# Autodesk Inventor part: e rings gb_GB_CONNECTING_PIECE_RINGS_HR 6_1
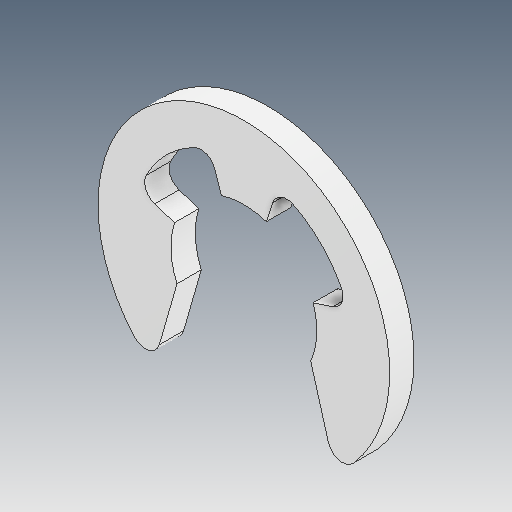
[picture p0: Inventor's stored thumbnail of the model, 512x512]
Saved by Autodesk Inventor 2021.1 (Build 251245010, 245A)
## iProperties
Created: 2021-05
Part Number: e rings gb_GB_CONNECTING_PIECE_RINGS_HR 6_1
Material: Ogólny
Document SubType Name: Modeling
Designer: user
Density: 1 g/cm^3
Appearance: Domyślna
Author: user
Revision Number: ÈÎºÎ
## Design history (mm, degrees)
feature "ÊäÈë1"
node "Bryła1"
